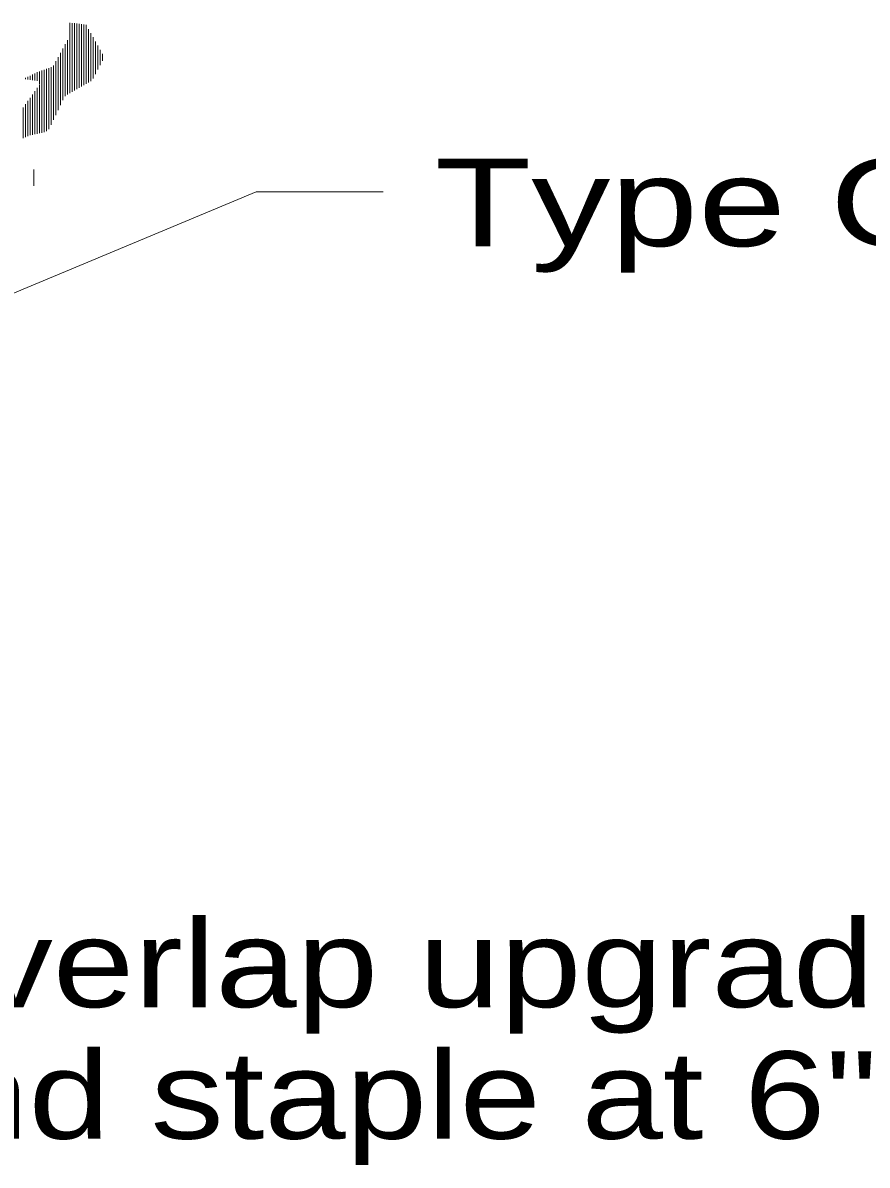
# Model space of a CAD drawing. Extents: x 1083.1 to 1117.1, y 719.4 to 741.4.
# Drawn here: x 1105.649 to 1107.154, y 720.73 to 722.767 of the extents above; entities that cross this region are included whole.
import ezdxf

# ---------------------------------------------------------------- set-up
doc = ezdxf.new("R2010")
doc.units = 0
doc.header["$LTSCALE"] = 0.062
doc.layers.add('1', color=7, linetype='Continuous', lineweight=13)

msp = doc.modelspace()

# ---------------------------------------------------------------- linework, layer by layer
at = {"layer": '1'}
for p, q in [((1105.73225, 722.64092), (1105.73225, 722.76658)), ((1105.73642, 722.64342), (1105.73642, 722.76617)), ((1105.74058, 722.64575), (1105.74058, 722.76575)), ((1105.74475, 722.64825), (1105.74475, 722.76525)), ((1105.74892, 722.65058), (1105.74892, 722.76483)), ((1105.75308, 722.65308), (1105.75308, 722.76442)), ((1105.75725, 722.6555), (1105.75725, 722.76392)), ((1105.76142, 722.65792), (1105.76142, 722.76275)), ((1105.76558, 722.66033), (1105.76558, 722.75542)), ((1105.76975, 722.66275), (1105.76975, 722.74808)), ((1105.72392, 722.63608), (1105.72392, 722.72842)), ((1105.72808, 722.63858), (1105.72808, 722.73592)), ((1105.77392, 722.66742), (1105.77392, 722.74075)), ((1105.77808, 722.67525), (1105.77808, 722.73342)), ((1105.71558, 722.62), (1105.71558, 722.71325)), ((1105.71975, 722.62875), (1105.71975, 722.72083)), ((1105.78225, 722.68325), (1105.78225, 722.72608)), ((1105.78642, 722.69108), (1105.78642, 722.71875)), ((1105.79058, 722.699), (1105.79058, 722.71142)), ((1105.69892, 722.58442), (1105.69892, 722.68725)), ((1105.70308, 722.59333), (1105.70308, 722.69058)), ((1105.70725, 722.60217), (1105.70725, 722.69808)), ((1105.71142, 722.61108), (1105.71142, 722.70567)), ((1105.65317, 722.66642), (1105.65317, 722.66825)), ((1105.65733, 722.66558), (1105.65733, 722.67025)), ((1105.6615, 722.66508), (1105.6615, 722.67233)), ((1105.66558, 722.66442), (1105.66558, 722.67442)), ((1105.66975, 722.66392), (1105.66975, 722.67642)), ((1105.67392, 722.66325), (1105.67392, 722.67842)), ((1105.67808, 722.65717), (1105.67808, 722.68)), ((1105.68225, 722.5705), (1105.68225, 722.68142)), ((1105.68642, 722.5715), (1105.68642, 722.68292)), ((1105.69058, 722.57325), (1105.69058, 722.68442)), ((1105.69475, 722.57717), (1105.69475, 722.68583)), ((1105.67392, 722.56867), (1105.67392, 722.65058)), ((1105.67808, 722.56967), (1105.67808, 722.65633)), ((1105.65733, 722.5645), (1105.65733, 722.62725)), ((1105.6615, 722.566), (1105.6615, 722.63308)), ((1105.66558, 722.56683), (1105.66558, 722.63892)), ((1105.66975, 722.56783), (1105.66975, 722.64475)), ((1105.649, 722.56117), (1105.649, 722.61567)), ((1105.65317, 722.56283), (1105.65317, 722.6215)), ((1105.66808, 722.47608), (1105.66808, 722.50533))]:
    msp.add_line(p, q, dxfattribs=at)
msp.add_lwpolyline([(1105.27608, 722.13608), (1106.0645, 722.46517), (1106.29133, 722.46517)], dxfattribs=at)

# ---------------------------------------------------------------- texts
for s, width, p in [('Type G mat', 1.35, (1106.38308, 722.36833)), ('Overlap upgrade mat by 1 1/2"[38]', 1.25, (1105.36892, 721.01125)), ('and staple at 6" [150] intervals.', 1.25, (1105.36892, 720.77658))]:
    msp.add_text(s, height=0.156, dxfattribs=dict(at, width=width)).set_placement(p)

doc.saveas('drawing.dxf')
